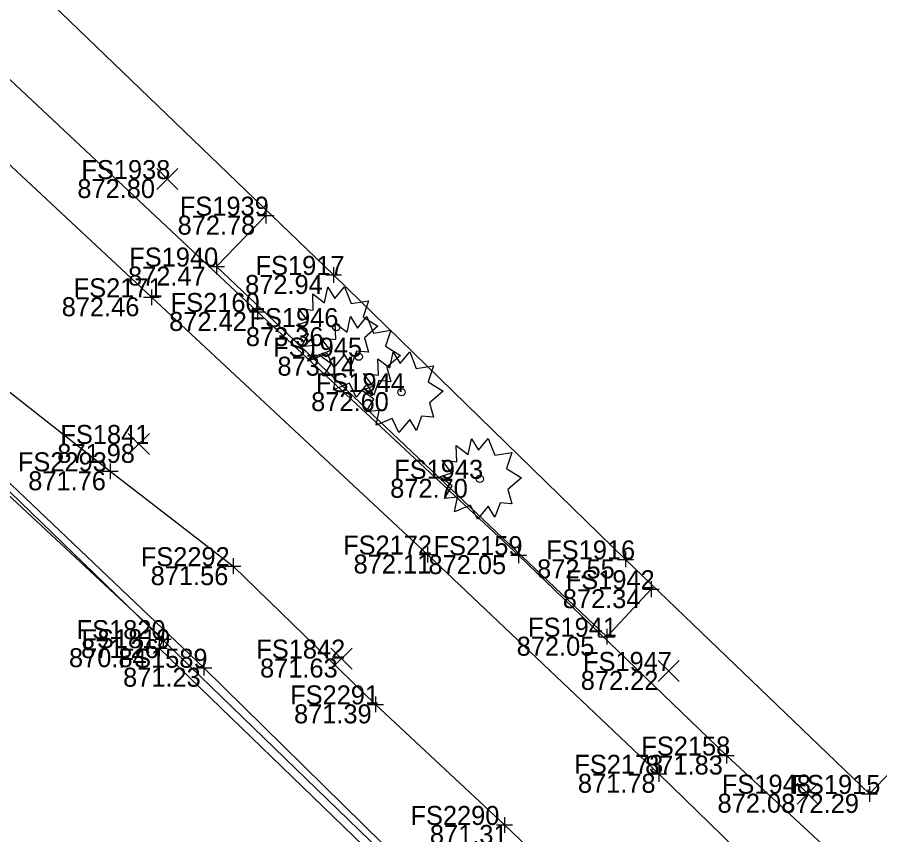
# Model space of a CAD drawing. Extents: x 1479420 to 1479833, y 379731 to 380103.
# Drawn here: x 1479593 to 1479647.5, y 379977 to 380028.7 of the extents above; entities that cross this region are included whole.
import ezdxf

# ---------------------------------------------------------------- set-up
doc = ezdxf.new("R2010")
doc.units = 0
for name, color, linetype in [('PV_X_Curb', 7, 'Continuous'), ('PV_X_Walk', 7, 'Continuous'), ('SV_X_Random_Point', 7, 'Continuous'), ('SV_X_Shot_Marker', 7, 'Continuous'), ('SV_X_Text_Elevation', 7, 'Continuous'), ('SV_X_Text_Name', 7, 'Continuous'), ('UT_X_Gas', 7, 'Continuous'), ('UT_X_Water', 7, 'Continuous'), ('VG_X_Cells', 7, 'Continuous'), ('VG_X_Flower_Bed', 7, 'Continuous')]:
    doc.layers.add(name, color=color, linetype=linetype)

msp = doc.modelspace()

# ---------------------------------------------------------------- linework, layer by layer
at = {"layer": 'PV_X_Curb'}
for points in [[(1479795.994, 380033.189), (1479773.609, 380022.189), (1479753.08, 380012.28), (1479732.582, 380002.187), (1479709.578, 379990.944), (1479686.038, 379979.568), (1479675.424, 379995.638), (1479673.845, 379997.042), (1479672.388, 379997.402), (1479671.072, 379997.477), (1479668.749, 379997.507), (1479666.577, 379997.444), (1479665.261, 379997.435), (1479663.761, 379996.907), (1479662.621, 379996.118), (1479646.813, 379979.589), (1479631.39, 379994.413), (1479612.948, 380012.393), (1479594.615, 380030.048), (1479574.047, 380049.976), (1479559.355, 380064.639), (1479550.33, 380073.358), (1479530.481, 380092.839), (1479523.351, 380099.687)], [(1479791.848, 380002.989), (1479773.254, 379993.873), (1479762.766, 379988.772), (1479738.122, 379976.643), (1479720.845, 379968.214), (1479698.694, 379957.239), (1479678.815, 379947.539), (1479674.951, 379945.56), (1479671.194, 379943.855), (1479668.836, 379942.929), (1479666.481, 379942.243), (1479664.295, 379941.704), (1479662.026, 379941.397), (1479659.994, 379941.512), (1479654.023, 379942.767), (1479648.758, 379945.101), (1479643.81, 379948.553), (1479642.638, 379949.516), (1479640.65, 379951.389), (1479638.379, 379953.495), (1479620.029, 379971.274), (1479601.931, 379988.801), (1479602.178, 379989.373), (1479582.142, 380008.015)], [(1479791.59, 380003.464), (1479772.982, 379994.381), (1479762.438, 379989.23), (1479737.891, 379977.225), (1479720.638, 379968.611), (1479698.71, 379957.883), (1479678.409, 379947.915), (1479674.816, 379946.157), (1479670.835, 379944.353), (1479668.74, 379943.532), (1479666.343, 379942.649), (1479664.179, 379942.195), (1479661.876, 379941.9), (1479659.999, 379941.971), (1479653.935, 379943.268), (1479649.182, 379945.527), (1479644.261, 379948.889), (1479643.432, 379949.993), (1479639.011, 379953.958), (1479638.818, 379953.848), (1479620.557, 379971.482), (1479582.44, 380008.391)]]:
    msp.add_lwpolyline(points, dxfattribs=at)
at = {"layer": 'PV_X_Walk'}
for points in [[(1479508.898, 380098.739), (1479528.424, 380079.592), (1479545.906, 380063.234), (1479563.416, 380046.674), (1479583.683, 380027.557), (1479601.433, 380010.982), (1479618.885, 379994.721), (1479633.506, 379980.864), (1479639.156, 379975.367), (1479642.136, 379972.51), (1479646.219, 379969.763), (1479649.18, 379968.041), (1479652.865, 379966.819), (1479656.787, 379966.268), (1479660.633, 379966.347), (1479661.26, 379962.343), (1479661.797, 379958.407), (1479662.398, 379954.371), (1479663.052, 379950.601), (1479663.586, 379946.455), (1479663.663, 379946.474), (1479664.156, 379942.194)], [(1479644.738, 379975.562), (1479637.768, 379982.016), (1479624.639, 379994.683), (1479608.139, 380010.055), (1479588.42, 380028.534)]]:
    msp.add_lwpolyline(points, dxfattribs=at)
at = {"layer": 'SV_X_Random_Point'}
for p, q in [((1479601.773, 380017.786), (1479603.107, 380019.121)), ((1479601.773, 380019.121), (1479603.107, 380017.786)), ((1479599.974, 380001.047), (1479601.308, 380002.382)), ((1479599.974, 380002.382), (1479601.308, 380001.047)), ((1479612.78, 379987.478), (1479614.114, 379988.813)), ((1479612.78, 379988.813), (1479614.114, 379987.478)), ((1479633.455, 379986.697), (1479634.789, 379988.032)), ((1479633.455, 379988.032), (1479634.789, 379986.697)), ((1479642.242, 379978.938), (1479643.576, 379980.273)), ((1479642.242, 379980.273), (1479643.576, 379978.938))]:
    msp.add_line(p, q, dxfattribs=at)
at = {"layer": 'SV_X_Shot_Marker'}
for p, q in [((1479608.662, 380016.641), (1479608.662, 380015.641)), ((1479608.162, 380016.141), (1479609.162, 380016.141)), ((1479608.662, 380016.141), (1479608.662, 380016.141)), ((1479605.549, 380013.424), (1479605.549, 380012.424)), ((1479605.049, 380012.924), (1479606.049, 380012.924)), ((1479605.549, 380012.924), (1479605.549, 380012.924)), ((1479612.948, 380012.893), (1479612.948, 380011.893)), ((1479612.448, 380012.393), (1479613.448, 380012.393)), ((1479612.948, 380012.393), (1479612.948, 380012.393)), ((1479601.433, 380011.482), (1479601.433, 380010.482)), ((1479600.933, 380010.982), (1479601.933, 380010.982)), ((1479601.433, 380010.982), (1479601.433, 380010.982)), ((1479608.139, 380010.555), (1479608.139, 380009.555)), ((1479607.639, 380010.055), (1479608.639, 380010.055)), ((1479608.139, 380010.055), (1479608.139, 380010.055)), ((1479598.835, 380000.483), (1479598.835, 379999.483)), ((1479598.335, 379999.983), (1479599.335, 379999.983)), ((1479598.835, 379999.983), (1479598.835, 379999.983)), ((1479618.885, 379995.221), (1479618.885, 379994.221)), ((1479624.639, 379995.183), (1479624.639, 379994.183)), ((1479631.39, 379994.913), (1479631.39, 379993.913)), ((1479606.591, 379994.485), (1479606.591, 379993.485)), ((1479618.385, 379994.721), (1479619.385, 379994.721)), ((1479618.885, 379994.721), (1479618.885, 379994.721)), ((1479624.139, 379994.683), (1479625.139, 379994.683)), ((1479624.639, 379994.683), (1479624.639, 379994.683)), ((1479630.89, 379994.413), (1479631.89, 379994.413)), ((1479631.39, 379994.413), (1479631.39, 379994.413)), ((1479606.091, 379993.985), (1479607.091, 379993.985)), ((1479606.591, 379993.985), (1479606.591, 379993.985)), ((1479633.023, 379993.031), (1479633.023, 379992.031)), ((1479632.523, 379992.531), (1479633.523, 379992.531)), ((1479633.023, 379992.531), (1479633.023, 379992.531)), ((1479630.214, 379990.027), (1479630.214, 379989.027)), ((1479602.178, 379989.873), (1479602.178, 379988.873)), ((1479629.714, 379989.527), (1479630.714, 379989.527)), ((1479630.214, 379989.527), (1479630.214, 379989.527)), ((1479601.678, 379989.373), (1479602.678, 379989.373)), ((1479601.931, 379989.301), (1479601.931, 379988.301)), ((1479602.178, 379989.373), (1479602.178, 379989.373)), ((1479601.431, 379988.801), (1479602.431, 379988.801)), ((1479601.931, 379988.801), (1479601.931, 379988.801)), ((1479604.754, 379988.067), (1479604.754, 379987.067)), ((1479604.254, 379987.567), (1479605.254, 379987.567)), ((1479604.754, 379987.567), (1479604.754, 379987.567)), ((1479615.604, 379985.749), (1479615.604, 379984.749)), ((1479615.104, 379985.249), (1479616.104, 379985.249)), ((1479615.604, 379985.249), (1479615.604, 379985.249)), ((1479637.768, 379982.516), (1479637.768, 379981.516)), ((1479637.268, 379982.016), (1479638.268, 379982.016)), ((1479637.768, 379982.016), (1479637.768, 379982.016)), ((1479633.506, 379981.364), (1479633.506, 379980.364)), ((1479633.006, 379980.864), (1479634.006, 379980.864)), ((1479633.506, 379980.864), (1479633.506, 379980.864)), ((1479646.313, 379979.589), (1479647.313, 379979.589)), ((1479646.813, 379980.089), (1479646.813, 379979.089)), ((1479646.813, 379979.589), (1479646.813, 379979.589)), ((1479623.747, 379978.129), (1479623.747, 379977.129)), ((1479623.247, 379977.629), (1479624.247, 379977.629)), ((1479623.747, 379977.629), (1479623.747, 379977.629))]:
    msp.add_line(p, q, dxfattribs=at)
at = {"layer": 'UT_X_Gas'}
msp.add_lwpolyline([(1479590.076, 380006.869), (1479598.835, 379999.983), (1479606.591, 379993.985), (1479615.604, 379985.249), (1479623.747, 379977.629), (1479632.184, 379969.538), (1479638.836, 379962.809), (1479646.785, 379955.438), (1479652.981, 379949.433), (1479657.465, 379945.964), (1479660.591, 379945.024), (1479670.935, 379949.08), (1479679.157, 379953.065), (1479685.442, 379955.742), (1479689.462, 379958.127), (1479696.956, 379963.013), (1479705.088, 379967.488), (1479713.465, 379971.226), (1479723.024, 379975.676), (1479732.065, 379980.116), (1479742.535, 379985.018)], dxfattribs=at)
at = {"layer": 'UT_X_Water'}
msp.add_lwpolyline([(1479586.915, 380004.501), (1479604.754, 379987.567), (1479618.613, 379973.926), (1479629.263, 379963.594), (1479633.713, 379960.434), (1479641.035, 379960.303), (1479643.418, 379958.357), (1479650.478, 379950.403), (1479653.168, 379946.48), (1479654.757, 379940.471), (1479659.938, 379935.366), (1479675.346, 379920.322), (1479682.752, 379913.809), (1479688.353, 379908.314)], dxfattribs=at)
at = {"layer": 'VG_X_Cells'}
for points in [[(1479613.032, 380010.904), (1479613.637, 380011.639), (1479614.052, 380010.586), (1479615.144, 380010.766), (1479614.805, 380009.754), (1479615.75, 380009.159), (1479614.894, 380008.424), (1479615.144, 380007.511), (1479614.39, 380007.579), (1479614.065, 380006.666), (1479613.637, 380007.357), (1479612.959, 380006.541), (1479612.53, 380007.427), (1479611.51, 380006.997), (1479611.702, 380007.939), (1479610.89, 380007.856), (1479611.364, 380008.646), (1479610.595, 380009.214), (1479611.334, 380009.477), (1479610.727, 380010.281), (1479611.659, 380010.171), (1479611.629, 380011.209), (1479612.382, 380010.641), (1479612.589, 380011.626), (1479613.032, 380010.904)], [(1479614.452, 380009.037), (1479615.057, 380009.772), (1479615.472, 380008.719), (1479616.564, 380008.899), (1479616.225, 380007.887), (1479617.17, 380007.292), (1479616.314, 380006.557), (1479616.564, 380005.644), (1479615.81, 380005.712), (1479615.485, 380004.799), (1479615.057, 380005.491), (1479614.379, 380004.674), (1479613.95, 380005.561), (1479612.93, 380005.131), (1479613.122, 380006.072), (1479612.31, 380005.989), (1479612.784, 380006.779), (1479612.015, 380007.347), (1479612.754, 380007.611), (1479612.147, 380008.414), (1479613.079, 380008.304), (1479613.049, 380009.342), (1479613.802, 380008.774), (1479614.009, 380009.759), (1479614.452, 380009.037)], [(1479617.15, 380006.795), (1479617.755, 380007.53), (1479618.17, 380006.477), (1479619.262, 380006.657), (1479618.923, 380005.645), (1479619.868, 380005.05), (1479619.012, 380004.315), (1479619.262, 380003.402), (1479618.508, 380003.47), (1479618.183, 380002.557), (1479617.755, 380003.248), (1479617.077, 380002.432), (1479616.648, 380003.318), (1479615.628, 380002.888), (1479615.82, 380003.83), (1479615.008, 380003.747), (1479615.482, 380004.537), (1479614.713, 380005.105), (1479615.452, 380005.368), (1479614.845, 380006.172), (1479615.777, 380006.062), (1479615.747, 380007.1), (1479616.5, 380006.532), (1479616.707, 380007.517), (1479617.15, 380006.795)], [(1479622.106, 380001.318), (1479622.711, 380002.053), (1479623.126, 380000.999), (1479624.218, 380001.179), (1479623.879, 380000.168), (1479624.824, 379999.573), (1479623.968, 379998.838), (1479624.218, 379997.924), (1479623.464, 379997.993), (1479623.139, 379997.079), (1479622.711, 379997.771), (1479622.033, 379996.954), (1479621.604, 379997.841), (1479620.584, 379997.411), (1479620.776, 379998.353), (1479619.964, 379998.269), (1479620.438, 379999.059), (1479619.669, 379999.628), (1479620.408, 379999.891), (1479619.801, 380000.694), (1479620.733, 380000.584), (1479620.703, 380001.623), (1479621.456, 380001.054), (1479621.663, 380002.039), (1479622.106, 380001.318)]]:
    msp.add_lwpolyline(points, dxfattribs=at)
for centre in [(1479613.116, 380009.095), (1479614.536, 380007.228), (1479617.234, 380004.986), (1479622.19, 379999.508)]:
    msp.add_circle(centre, 0.23, dxfattribs=at)
at = {"layer": 'VG_X_Flower_Bed'}
msp.add_lwpolyline([(1479608.662, 380016.141), (1479605.549, 380012.924), (1479630.214, 379989.527), (1479633.023, 379992.531)], dxfattribs=at)

# ---------------------------------------------------------------- texts
at = {"layer": 'SV_X_Text_Elevation'}
for s, p in [('872.80', (1479596.752, 380017.253)), ('872.78', (1479603.088, 380014.941)), ('872.47', (1479599.956, 380011.724)), ('872.94', (1479607.355, 380011.193)), ('872.46', (1479595.764, 380009.782)), ('872.42', (1479602.555, 380008.855)), ('873.36', (1479607.401, 380007.894)), ('873.14', (1479609.398, 380006.027)), ('872.60', (1479611.528, 380003.785)), ('871.98', (1479595.483, 380000.514)), ('871.76', (1479593.649, 379998.783)), ('872.70', (1479616.522, 379998.308)), ('872.11', (1479614.208, 379993.521)), ('872.05', (1479618.942, 379993.483)), ('872.55', (1479625.806, 379993.213)), ('871.56', (1479601.386, 379992.785)), ('872.34', (1479627.43, 379991.331)), ('871.26', (1479596.992, 379988.173)), ('872.05', (1479624.517, 379988.327)), ('870.84', (1479596.224, 379987.601)), ('871.63', (1479608.298, 379986.946)), ('871.23', (1479599.643, 379986.367)), ('872.22', (1479628.566, 379986.164)), ('871.39', (1479610.446, 379984.049)), ('871.83', (1479632.638, 379980.816)), ('871.78', (1479628.386, 379979.664)), ('872.03', (1479637.212, 379978.405)), ('872.29', (1479641.239, 379978.389)), ('871.31', (1479619.032, 379976.429))]:
    msp.add_text(s, height=1.2, dxfattribs=at).set_placement(p)
at = {"layer": 'SV_X_Text_Name'}
for s, p in [('FS1938', (1479597.008, 380018.453)), ('FS1939', (1479603.23, 380016.141)), ('FS1940', (1479600.032, 380012.924)), ('FS1917', (1479608.017, 380012.393)), ('FS2171', (1479596.52, 380010.982)), ('FS2160', (1479602.65, 380010.055)), ('FS1946', (1479607.628, 380009.094)), ('FS1945', (1479609.124, 380007.227)), ('FS1944', (1479611.831, 380004.985)), ('FS1841', (1479595.681, 380001.714)), ('FS2293', (1479592.996, 379999.983)), ('FS1943', (1479616.778, 379999.508)), ('FS2172', (1479613.547, 379994.721)), ('FS2159', (1479619.264, 379994.683)), ('FS1916', (1479626.384, 379994.413)), ('FS2292', (1479600.762, 379993.985)), ('FS1942', (1479627.619, 379992.531)), ('FS1820', (1479596.708, 379989.373)), ('FS1941', (1479625.235, 379989.527)), ('FS1819', (1479597.01, 379988.801)), ('FS1842', (1479608.062, 379988.146)), ('FS1589', (1479599.36, 379987.567)), ('FS1947', (1479628.709, 379987.364)), ('FS2291', (1479610.199, 379985.249)), ('FS2158', (1479632.393, 379982.016)), ('FS2173', (1479628.159, 379980.864)), ('FS1948', (1479637.486, 379979.605)), ('FS1915', (1479641.882, 379979.589)), ('FS2290', (1479617.804, 379977.629))]:
    msp.add_text(s, height=1.2, dxfattribs=at).set_placement(p)

doc.saveas('drawing.dxf')
